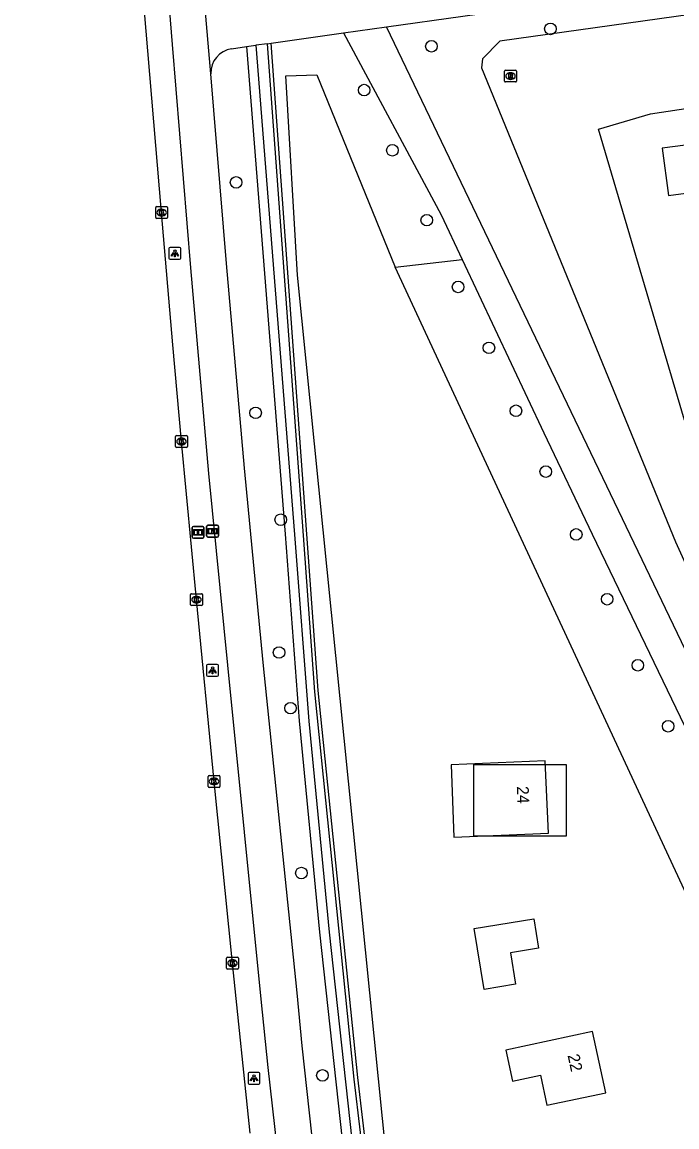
# Model space of a CAD drawing. Extents: x 159451 to 160663, y 388402 to 389723.
# Drawn here: x 159455.9 to 159511.2, y 389199.9 to 389293.3 of the extents above; entities that cross this region are included whole.
import ezdxf

# ---------------------------------------------------------------- set-up
doc = ezdxf.new("R2010")
doc.units = 0
for name, color, linetype in [('IMGEO_Boom', 7, 'Continuous'), ('IMGEO_Bouwland', 7, 'Continuous'), ('IMGEO_Fietspad_gesloten', 7, 'Continuous'), ('IMGEO_Grasland_overig', 7, 'Continuous'), ('IMGEO_Greppel_droge_sloot', 7, 'Continuous'), ('IMGEO_Groenvoorziening', 7, 'Continuous'), ('IMGEO_Informatiebord', 7, 'Continuous'), ('IMGEO_Kolk', 7, 'Continuous'), ('IMGEO_Lichtpunt', 7, 'Continuous'), ('IMGEO_Meer_plas_ven_vijver', 7, 'Continuous'), ('IMGEO_Pand', 7, 'Continuous'), ('IMGEO_Pand_nummerreeks', 7, 'Continuous'), ('IMGEO_Pand_vergunning_verleend', 7, 'Continuous'), ('IMGEO_Rijbaan_lokaal_gesloten', 7, 'Continuous'), ('IMGEO_Rijbaan_regionaal_gesloten', 7, 'Continuous'), ('IMGEO_Rioolput', 7, 'Continuous')]:
    doc.layers.add(name, color=color, linetype=linetype)

msp = doc.modelspace()

# ---------------------------------------------------------------- linework, layer by layer
at = {"layer": 'IMGEO_Boom'}
for centre in [(159500.562, 389292.694), (159490.513, 389291.221), (159484.833, 389287.523), (159487.212, 389282.438), (159474.017, 389279.731), (159490.119, 389276.537), (159492.765, 389270.894), (159495.369, 389265.75), (159475.667, 389260.259), (159497.654, 389260.432), (159500.169, 389255.291), (159477.78, 389251.227), (159502.742, 389249.985), (159505.355, 389244.513), (159477.641, 389240.014), (159507.942, 389238.933), (159478.609, 389235.309), (159510.507, 389233.782), (159479.525, 389221.382), (159481.307, 389204.286)]:
    msp.add_circle(centre, 0.489, dxfattribs=at)
at = {"layer": 'IMGEO_Bouwland'}
for points in [[(159495.943, 389125.547), (159492.959, 389147.253), (159490.78, 389160.929), (159488.551, 389179.124), (159479.211, 389271.897), (159478.228, 389288.738), (159480.836, 389288.81), (159487.441, 389272.575)], [(159539.156, 389122.203), (159538.081, 389141.023), (159537.243, 389155.693), (159534.303, 389168.702), (159530.224, 389180.456), (159487.441, 389272.575)]]:
    msp.add_lwpolyline(points, dxfattribs=at)
at = {"layer": 'IMGEO_Fietspad_gesloten'}
for points in [[(159455.942, 389525.002), (159456.038, 389522.126), (159456.372, 389512.313), (159456.916, 389496.35), (159457.955, 389465.071), (159459.294, 389436.93), (159461.071, 389403.687), (159462.508, 389376.402), (159464.342, 389348.5), (159465.649, 389329.916), (159467.063, 389310.472), (159468.609, 389291.384), (159470.151, 389272.51), (159471.683, 389255.143), (159473.293, 389238.955), (159476.115, 389210.723), (159476.688, 389204.954), (159478.244, 389191.231), (159479.81, 389178.066)], [(159492.482, 389125.078), (159491.057, 389131.504), (159487.963, 389147.366), (159485.138, 389162.462), (159483.697, 389171.161), (159482.691, 389178.486), (159481.255, 389191.613), (159479.595, 389206.774), (159479.167, 389211.269), (159476.315, 389239.166), (159474.73, 389255.582), (159473.199, 389272.868), (159471.882, 389288.893)]]:
    msp.add_lwpolyline(points, dxfattribs=at)
at = {"layer": 'IMGEO_Grasland_overig'}
for points in [[(159483.087, 389292.351), (159491.324, 389276.977), (159493.1, 389273.212)], [(159552.375, 389144.269), (159550.196, 389160.656), (159546.355, 389164.126), (159540.689, 389183.824), (159539.945, 389186.409), (159538.67, 389189.107), (159536.847, 389188.304), (159486.712, 389292.863)], [(159493.1, 389273.212), (159500, 389258.58), (159504.093, 389250), (159534.245, 389187.399), (159541.062, 389164.374)]]:
    msp.add_lwpolyline(points, dxfattribs=at)
at = {"layer": 'IMGEO_Greppel_droge_sloot'}
for points in [[(159475.691, 389291.305), (159478.961, 389249.969), (159480.156, 389234.213), (159481.882, 389216.377), (159483.778, 389198.834)], [(159486.114, 389185.938), (159483.986, 389203.971), (159480.658, 389236.689), (159479.697, 389249.885), (159476.671, 389291.444)]]:
    msp.add_lwpolyline(points, dxfattribs=at)
at = {"layer": 'IMGEO_Groenvoorziening'}
for points in [[(159474.893, 389291.192), (159478.151, 389250), (159479.346, 389234.239), (159481.073, 389216.395), (159482.97, 389198.843), (159485.767, 389176.684), (159487.05, 389167.999), (159488.037, 389162.469), (159490.153, 389153.348), (159490.295, 389153.124), (159490.458, 389152.949), (159490.624, 389152.875), (159490.9, 389152.917), (159491.057, 389153.021), (159491.194, 389153.27), (159491.245, 389153.512), (159490.896, 389156.395), (159489.602, 389164.953), (159488.663, 389170.113), (159486.412, 389186.084), (159484.285, 389204.106), (159480.958, 389236.812), (159479.998, 389250), (159476.978, 389291.487)], [(159487.441, 389272.575), (159493.1, 389273.212)]]:
    msp.add_lwpolyline(points, dxfattribs=at)
at = {"layer": 'IMGEO_Informatiebord'}
for p, q in [((159470.304, 389249.758), (159470.304, 389250.558)), ((159470.304, 389250.558), (159470.304, 389249.758)), ((159470.404, 389250.658), (159471.194, 389250.658)), ((159471.194, 389250.658), (159470.404, 389250.658)), ((159471.294, 389250.558), (159471.294, 389249.758)), ((159471.294, 389249.758), (159471.294, 389250.558)), ((159471.529, 389249.859), (159471.529, 389250.659)), ((159471.529, 389250.659), (159471.529, 389249.859)), ((159471.629, 389250.759), (159472.419, 389250.759)), ((159472.419, 389250.759), (159471.629, 389250.759)), ((159472.519, 389250.659), (159472.519, 389249.859)), ((159472.519, 389249.859), (159472.519, 389250.659)), ((159471.194, 389249.658), (159470.404, 389249.658)), ((159470.404, 389249.658), (159471.194, 389249.658)), ((159472.419, 389249.759), (159471.629, 389249.759)), ((159471.629, 389249.759), (159472.419, 389249.759))]:
    msp.add_line(p, q, dxfattribs=at)
for points in [[(159470.405, 389250.39), (159471.193, 389250.39), (159471.193, 389249.926), (159470.405, 389249.926), (159470.405, 389250.39)], [(159470.47, 389250.325), (159470.47, 389249.991), (159470.745, 389249.991), (159470.746, 389250.204), (159470.85, 389250.205), (159470.851, 389249.991), (159471.128, 389249.991), (159471.128, 389250.325), (159470.852, 389250.325), (159470.852, 389250.245), (159470.746, 389250.245), (159470.746, 389250.325), (159470.47, 389250.325)], [(159471.63, 389250.491), (159472.418, 389250.491), (159472.418, 389250.027), (159471.63, 389250.027), (159471.63, 389250.491)], [(159471.695, 389250.426), (159471.695, 389250.092), (159471.97, 389250.092), (159471.971, 389250.305), (159472.075, 389250.306), (159472.076, 389250.092), (159472.353, 389250.092), (159472.353, 389250.426), (159472.077, 389250.426), (159472.077, 389250.346), (159471.971, 389250.346), (159471.971, 389250.426), (159471.695, 389250.426)]]:
    msp.add_lwpolyline(points, dxfattribs=at)
for centre, start, end in [((159470.404, 389250.558), 90, 180), ((159470.404, 389250.558), 90, 180), ((159471.194, 389250.558), 0, 90), ((159471.194, 389250.558), 360, 90), ((159471.629, 389250.659), 90, 180), ((159471.629, 389250.659), 90, 180), ((159472.419, 389250.659), 0, 90), ((159472.419, 389250.659), 360, 90), ((159470.404, 389249.758), 180, 270), ((159470.404, 389249.758), 180, 270), ((159471.194, 389249.758), 270, 0), ((159471.194, 389249.758), 270, 0), ((159471.629, 389249.859), 180, 270), ((159471.629, 389249.859), 180, 270), ((159472.419, 389249.859), 270, 0), ((159472.419, 389249.859), 270, 0)]:
    msp.add_arc(centre, 0.1, start, end, dxfattribs=at)
at = {"layer": 'IMGEO_Kolk'}
for p, q in [((159467.227, 389276.753), (159467.227, 389277.605)), ((159467.302, 389277.679), (159468.154, 389277.679)), ((159467.715, 389277.459), (159467.74, 389277.459)), ((159468.228, 389277.605), (159468.228, 389276.753)), ((159468.154, 389276.679), (159467.302, 389276.679)), ((159467.738, 389276.899), (159467.713, 389276.899)), ((159468.904, 389257.41), (159468.904, 389258.262)), ((159468.979, 389258.336), (159469.831, 389258.336)), ((159469.392, 389258.116), (159469.417, 389258.116)), ((159469.905, 389258.262), (159469.905, 389257.41)), ((159469.831, 389257.336), (159468.979, 389257.336)), ((159469.415, 389257.556), (159469.39, 389257.556)), ((159470.172, 389244.051), (159470.172, 389244.903)), ((159470.247, 389244.977), (159471.099, 389244.977)), ((159470.66, 389244.757), (159470.685, 389244.757)), ((159471.173, 389244.903), (159471.173, 389244.051)), ((159471.099, 389243.977), (159470.247, 389243.977)), ((159470.683, 389244.197), (159470.658, 389244.197)), ((159471.727, 389229.621), (159472.579, 389229.621)), ((159471.652, 389228.695), (159471.652, 389229.547)), ((159472.163, 389228.841), (159472.138, 389228.841)), ((159472.14, 389229.401), (159472.165, 389229.401)), ((159472.653, 389229.547), (159472.653, 389228.695)), ((159472.579, 389228.621), (159471.727, 389228.621)), ((159473.212, 389213.341), (159473.212, 389214.193)), ((159473.287, 389214.267), (159474.139, 389214.267)), ((159473.7, 389214.047), (159473.725, 389214.047)), ((159474.213, 389214.193), (159474.213, 389213.341)), ((159474.139, 389213.267), (159473.287, 389213.267)), ((159473.723, 389213.487), (159473.698, 389213.487))]:
    msp.add_line(p, q, dxfattribs=at)
for points in [[(159467.227, 389276.753), (159467.227, 389277.605)], [(159467.302, 389277.679), (159468.154, 389277.679)], [(159467.548, 389277.379), (159467.671, 389277.379), (159467.671, 389277.228), (159467.801, 389277.379), (159467.965, 389277.379), (159467.819, 389277.228), (159467.972, 389276.979), (159467.82, 389276.979), (159467.735, 389277.143), (159467.671, 389277.076), (159467.671, 389276.979), (159467.548, 389276.979), (159467.548, 389277.379)], [(159468.228, 389277.605), (159468.228, 389276.753)], [(159468.154, 389276.679), (159467.302, 389276.679)], [(159468.904, 389257.41), (159468.904, 389258.262)], [(159468.979, 389258.336), (159469.831, 389258.336)], [(159469.225, 389258.036), (159469.348, 389258.036), (159469.348, 389257.885), (159469.478, 389258.036), (159469.642, 389258.036), (159469.496, 389257.885), (159469.649, 389257.636), (159469.497, 389257.636), (159469.412, 389257.8), (159469.348, 389257.733), (159469.348, 389257.636), (159469.225, 389257.636), (159469.225, 389258.036)], [(159469.905, 389258.262), (159469.905, 389257.41)], [(159469.831, 389257.336), (159468.979, 389257.336)], [(159470.172, 389244.051), (159470.172, 389244.903)], [(159470.247, 389244.977), (159471.099, 389244.977)], [(159470.493, 389244.677), (159470.616, 389244.677), (159470.616, 389244.526), (159470.746, 389244.677), (159470.91, 389244.677), (159470.764, 389244.526), (159470.917, 389244.277), (159470.765, 389244.277), (159470.68, 389244.441), (159470.616, 389244.374), (159470.616, 389244.277), (159470.493, 389244.277), (159470.493, 389244.677)], [(159471.173, 389244.903), (159471.173, 389244.051)], [(159471.099, 389243.977), (159470.247, 389243.977)], [(159471.727, 389229.621), (159472.579, 389229.621)], [(159471.652, 389228.695), (159471.652, 389229.547)], [(159471.973, 389229.321), (159472.096, 389229.321), (159472.096, 389229.17), (159472.226, 389229.321), (159472.39, 389229.321), (159472.244, 389229.17), (159472.397, 389228.921), (159472.245, 389228.921), (159472.16, 389229.085), (159472.096, 389229.018), (159472.096, 389228.921), (159471.973, 389228.921), (159471.973, 389229.321)], [(159472.653, 389229.547), (159472.653, 389228.695)], [(159472.579, 389228.621), (159471.727, 389228.621)], [(159473.212, 389213.341), (159473.212, 389214.193)], [(159473.287, 389214.267), (159474.139, 389214.267)], [(159473.533, 389213.967), (159473.656, 389213.967), (159473.656, 389213.816), (159473.786, 389213.967), (159473.95, 389213.967), (159473.804, 389213.816), (159473.957, 389213.567), (159473.805, 389213.567), (159473.72, 389213.731), (159473.656, 389213.664), (159473.656, 389213.567), (159473.533, 389213.567), (159473.533, 389213.967)], [(159474.213, 389214.193), (159474.213, 389213.341)], [(159474.139, 389213.267), (159473.287, 389213.267)]]:
    msp.add_lwpolyline(points, dxfattribs=at)
for centre, start, end in [((159467.304, 389277.603), 91.55205, 178.44795), ((159467.304, 389277.603), 91.55205, 178.44795), ((159468.152, 389277.603), 1.55205, 88.44795), ((159468.152, 389277.603), 1.55205, 88.44795), ((159467.304, 389276.755), 181.55205, 268.44795), ((159467.304, 389276.755), 181.55205, 268.44795), ((159468.152, 389276.755), 271.55205, 358.44795), ((159468.152, 389276.755), 271.55205, 358.44795), ((159468.981, 389258.26), 91.55205, 178.44795), ((159468.981, 389258.26), 91.55205, 178.44795), ((159469.829, 389258.26), 1.55205, 88.44795), ((159469.829, 389258.26), 1.55205, 88.44795), ((159468.981, 389257.412), 181.55205, 268.44795), ((159468.981, 389257.412), 181.55205, 268.44795), ((159469.829, 389257.412), 271.55205, 358.44795), ((159469.829, 389257.412), 271.55205, 358.44795), ((159470.249, 389244.901), 91.55205, 178.44795), ((159470.249, 389244.901), 91.55205, 178.44795), ((159471.097, 389244.901), 1.55205, 88.44795), ((159471.097, 389244.901), 1.55205, 88.44795), ((159470.249, 389244.053), 181.55205, 268.44795), ((159470.249, 389244.053), 181.55205, 268.44795), ((159471.097, 389244.053), 271.55205, 358.44795), ((159471.097, 389244.053), 271.55205, 358.44795), ((159471.729, 389229.545), 91.55205, 178.44795), ((159471.729, 389229.545), 91.55205, 178.44795), ((159472.577, 389229.545), 1.55205, 88.44795), ((159472.577, 389229.545), 1.55205, 88.44795), ((159471.729, 389228.697), 181.55205, 268.44795), ((159471.729, 389228.697), 181.55205, 268.44795), ((159472.577, 389228.697), 271.55205, 358.44795), ((159472.577, 389228.697), 271.55205, 358.44795), ((159473.289, 389214.191), 91.55205, 178.44795), ((159473.289, 389214.191), 91.55205, 178.44795), ((159474.137, 389214.191), 1.55205, 88.44795), ((159474.137, 389214.191), 1.55205, 88.44795), ((159473.289, 389213.343), 181.55205, 268.44795), ((159473.289, 389213.343), 181.55205, 268.44795), ((159474.137, 389213.343), 271.55205, 358.44795), ((159474.137, 389213.343), 271.55205, 358.44795)]:
    msp.add_arc(centre, 0.0765, start, end, dxfattribs=at)
for centre, major_axis, ratio, start_param, end_param in [((159467.714, 389277.179), (-0.387, 0.002), 0.722429, 4.712389, 7.853982), ((159467.739, 389277.179), (-0.39, 0.002), 0.717154, 1.570796, 4.712389), ((159469.391, 389257.836), (-0.387, 0.002), 0.722429, 4.712389, 7.853982), ((159469.416, 389257.836), (-0.39, 0.002), 0.717154, 1.570796, 4.712389), ((159470.659, 389244.477), (-0.387, 0.002), 0.722429, 4.712389, 7.853982), ((159470.684, 389244.477), (-0.39, 0.002), 0.717154, 1.570796, 4.712389), ((159472.139, 389229.121), (-0.387, 0.002), 0.722429, 4.712389, 7.853982), ((159472.164, 389229.121), (-0.39, 0.002), 0.717154, 1.570796, 4.712389), ((159473.699, 389213.767), (-0.387, 0.002), 0.722429, 4.712389, 7.853982), ((159473.724, 389213.767), (-0.39, 0.002), 0.717154, 1.570796, 4.712389)]:
    msp.add_ellipse(centre, major_axis=major_axis, ratio=ratio, start_param=start_param, end_param=end_param, dxfattribs=at)
at = {"layer": 'IMGEO_Lichtpunt'}
for p, q in [((159468.346, 389274.13), (159468.346, 389273.323)), ((159468.346, 389274.13), (159468.346, 389273.323)), ((159469.248, 389274.225), (159468.44, 389274.225)), ((159469.248, 389274.225), (159468.44, 389274.225)), ((159469.342, 389273.323), (159469.342, 389274.13)), ((159469.342, 389273.323), (159469.342, 389274.13)), ((159468.44, 389273.229), (159469.248, 389273.229)), ((159468.44, 389273.229), (159469.248, 389273.229)), ((159472.429, 389239.001), (159471.621, 389239.001)), ((159472.429, 389239.001), (159471.621, 389239.001)), ((159471.527, 389238.906), (159471.527, 389238.099)), ((159471.527, 389238.906), (159471.527, 389238.099)), ((159471.621, 389238.005), (159472.429, 389238.005)), ((159471.621, 389238.005), (159472.429, 389238.005)), ((159472.523, 389238.099), (159472.523, 389238.906)), ((159472.523, 389238.099), (159472.523, 389238.906)), ((159475.029, 389204.443), (159475.029, 389203.636)), ((159475.029, 389204.443), (159475.029, 389203.636)), ((159475.931, 389204.538), (159475.123, 389204.538)), ((159475.931, 389204.538), (159475.123, 389204.538)), ((159476.025, 389203.636), (159476.025, 389204.443)), ((159476.025, 389203.636), (159476.025, 389204.443)), ((159475.123, 389203.542), (159475.931, 389203.542)), ((159475.123, 389203.542), (159475.931, 389203.542))]:
    msp.add_line(p, q, dxfattribs=at)
for points in [[(159468.72, 389273.794), (159468.759, 389273.766), (159468.571, 389273.504), (159468.533, 389273.531), (159468.72, 389273.794)], [(159468.822, 389273.746), (159468.869, 389273.746), (159468.869, 389273.424), (159468.822, 389273.424), (159468.822, 389273.746)], [(159468.932, 389273.766), (159468.97, 389273.793), (159469.157, 389273.531), (159469.118, 389273.503), (159468.932, 389273.766)], [(159471.901, 389238.57), (159471.94, 389238.542), (159471.752, 389238.28), (159471.714, 389238.307), (159471.901, 389238.57)], [(159472.003, 389238.522), (159472.05, 389238.522), (159472.05, 389238.2), (159472.003, 389238.2), (159472.003, 389238.522)], [(159472.113, 389238.542), (159472.151, 389238.569), (159472.338, 389238.307), (159472.299, 389238.279), (159472.113, 389238.542)], [(159475.403, 389204.107), (159475.442, 389204.079), (159475.254, 389203.817), (159475.216, 389203.844), (159475.403, 389204.107)], [(159475.505, 389204.059), (159475.552, 389204.059), (159475.552, 389203.737), (159475.505, 389203.737), (159475.505, 389204.059)], [(159475.615, 389204.079), (159475.653, 389204.106), (159475.84, 389203.844), (159475.801, 389203.816), (159475.615, 389204.079)]]:
    msp.add_lwpolyline(points, dxfattribs=at)
for centre in [(159468.845, 389273.928), (159472.026, 389238.704), (159475.528, 389204.241)]:
    msp.add_circle(centre, 0.0994, dxfattribs=at)
for centre, start, end in [((159468.44, 389274.13), 90, 180), ((159468.44, 389274.13), 90, 180), ((159469.248, 389274.13), 0, 90), ((159469.248, 389274.13), 0, 90), ((159468.44, 389273.323), 180, 270), ((159468.44, 389273.323), 180, 270), ((159469.248, 389273.323), 270, 0), ((159469.248, 389273.323), 270, 360), ((159471.621, 389238.906), 90, 180), ((159471.621, 389238.906), 90, 180), ((159472.429, 389238.906), 0, 90), ((159472.429, 389238.906), 0, 90), ((159471.621, 389238.099), 180, 270), ((159471.621, 389238.099), 180, 270), ((159472.429, 389238.099), 270, 0), ((159472.429, 389238.099), 270, 360), ((159475.123, 389204.443), 90, 180), ((159475.123, 389204.443), 90, 180), ((159475.931, 389204.443), 0, 90), ((159475.931, 389204.443), 0, 90), ((159475.123, 389203.636), 180, 270), ((159475.123, 389203.636), 180, 270), ((159475.931, 389203.636), 270, 0), ((159475.931, 389203.636), 270, 360)]:
    msp.add_arc(centre, 0.0946, start, end, dxfattribs=at)
at = {"layer": 'IMGEO_Meer_plas_ven_vijver'}
msp.add_lwpolyline([(159521.069, 389241.65), (159518.659, 389246.126), (159517.22, 389247.851), (159515.886, 389256.055), (159514.744, 389257.84), (159511.894, 389259.653), (159504.61, 389284.226), (159509.011, 389285.515), (159523.74, 389287.733), (159521.85, 389295.267), (159496.278, 389291.663), (159494.831, 389290.177), (159494.743, 389289.39), (159511.127, 389249.352), (159515.724, 389239.283), (159521.069, 389241.65)], dxfattribs=at)
at = {"layer": 'IMGEO_Pand'}
for points in [[(159520.557, 389279.914), (159520.041, 389283.908), (159510.008, 389282.625), (159510.521, 389278.616), (159512.856, 389278.918)], [(159500.128, 389230.864), (159492.187, 389230.515), (159492.414, 389224.419), (159500.402, 389224.762), (159500.128, 389230.864)], [(159504.128, 389207.999), (159496.8, 389206.424), (159497.364, 389203.804), (159499.721, 389204.311), (159500.269, 389201.761), (159505.241, 389202.823), (159504.128, 389207.999)]]:
    msp.add_lwpolyline(points, dxfattribs=at)
at = {"layer": 'IMGEO_Pand_vergunning_verleend'}
for points in [[(159494.105, 389224.51), (159494.105, 389230.558), (159501.904, 389230.558), (159501.904, 389224.51), (159494.105, 389224.51)], [(159494.132, 389216.702), (159499.161, 389217.522), (159499.569, 389215.022), (159497.187, 389214.633), (159497.619, 389211.986), (159494.971, 389211.554), (159494.132, 389216.702)]]:
    msp.add_lwpolyline(points, dxfattribs=at)
at = {"layer": 'IMGEO_Rijbaan_lokaal_gesloten'}
for points in [[(159486.712, 389292.863), (159493.172, 389293.777), (159521.25, 389297.74)], [(159471.882, 389288.893), (159471.345, 389295.068)], [(159476.978, 389291.487), (159483.087, 389292.351)], [(159483.087, 389292.351), (159486.712, 389292.863)], [(159473.627, 389291.013), (159474.893, 389291.192)], [(159474.893, 389291.192), (159475.691, 389291.305)], [(159476.671, 389291.444), (159475.691, 389291.305)], [(159476.671, 389291.444), (159476.978, 389291.487)]]:
    msp.add_lwpolyline(points, dxfattribs=at)
msp.add_arc((159473.932, 389288.984), 2.052, 98.53826, 182.54525, dxfattribs=at)
at = {"layer": 'IMGEO_Rijbaan_regionaal_gesloten'}
msp.add_lwpolyline([(159475.213, 389199.409), (159473.713, 389213.767), (159472.153, 389229.121), (159470.673, 389244.477), (159469.405, 389257.836), (159468.669, 389266.005), (159467.728, 389277.179), (159466.081, 389296.525), (159464.392, 389316.843), (159462.91, 389337.218), (159462.193, 389348.076), (159461.584, 389357.574), (159460.45, 389376.955), (159459.237, 389397.341)], dxfattribs=at)
at = {"layer": 'IMGEO_Rioolput'}
for p, q in [((159496.696, 389288.283), (159496.696, 389289.135)), ((159496.771, 389289.209), (159497.623, 389289.209)), ((159497.207, 389288.429), (159497.182, 389288.429)), ((159497.184, 389288.989), (159497.209, 389288.989)), ((159497.697, 389289.135), (159497.697, 389288.283)), ((159497.623, 389288.209), (159496.771, 389288.209))]:
    msp.add_line(p, q, dxfattribs=at)
for points in [[(159496.696, 389288.283), (159496.696, 389289.135)], [(159496.771, 389289.209), (159497.623, 389289.209)], [(159497.285, 389288.907), (159497.033, 389288.909), (159497.033, 389288.509)], [(159497.033, 389288.509), (159497.157, 389288.509), (159497.157, 389288.671), (159497.168, 389288.671)], [(159497.211, 389288.828), (159497.157, 389288.828), (159497.157, 389288.747)], [(159497.157, 389288.747), (159497.209, 389288.747)], [(159497.215, 389288.642), (159497.286, 389288.509), (159497.426, 389288.509), (159497.361, 389288.635)], [(159497.697, 389289.135), (159497.697, 389288.283)], [(159497.623, 389288.209), (159496.771, 389288.209)]]:
    msp.add_lwpolyline(points, dxfattribs=at)
for centre, radius, start, end in [((159496.773, 389289.133), 0.0765, 91.55205, 178.44795), ((159496.773, 389289.133), 0.0765, 91.55205, 178.44795), ((159497.167, 389288.618), 0.0533, 26.02933, 88.69889), ((159497.193, 389288.936), 0.19, 274.7715, 282.96867), ((159497.217, 389288.732), 0.0964, 77.00612, 93.18647), ((159497.231, 389288.789), 0.0378, 276.66336, 79.67722), ((159497.284, 389288.797), 0.109, 350.36119, 89.41601), ((159497.282, 389288.797), 0.112, 277.58423, 350.98172), ((159497.266, 389288.582), 0.108, 29.51342, 73.79051), ((159497.621, 389289.133), 0.0765, 1.55205, 88.44795), ((159497.621, 389289.133), 0.0765, 1.55205, 88.44795), ((159496.773, 389288.285), 0.0765, 181.55205, 268.44795), ((159496.773, 389288.285), 0.0765, 181.55205, 268.44795), ((159497.621, 389288.285), 0.0765, 271.55205, 358.44795), ((159497.621, 389288.285), 0.0765, 271.55205, 358.44795)]:
    msp.add_arc(centre, radius, start, end, dxfattribs=at)
for centre, major_axis, ratio, start_param, end_param in [((159497.183, 389288.709), (-0.387, 0.002), 0.722429, 4.712389, 7.853982), ((159497.208, 389288.709), (-0.39, 0.002), 0.717154, 1.570796, 4.712389)]:
    msp.add_ellipse(centre, major_axis=major_axis, ratio=ratio, start_param=start_param, end_param=end_param, dxfattribs=at)

# ---------------------------------------------------------------- texts
at = {"layer": 'IMGEO_Pand_nummerreeks'}
for s, rotation, p in [('24', 272.57237, (159497.722, 389228.703)), ('22', 282.13504, (159502.004, 389205.985))]:
    msp.add_text(s, height=1, rotation=rotation, dxfattribs=at).set_placement(p)

doc.saveas('drawing.dxf')
